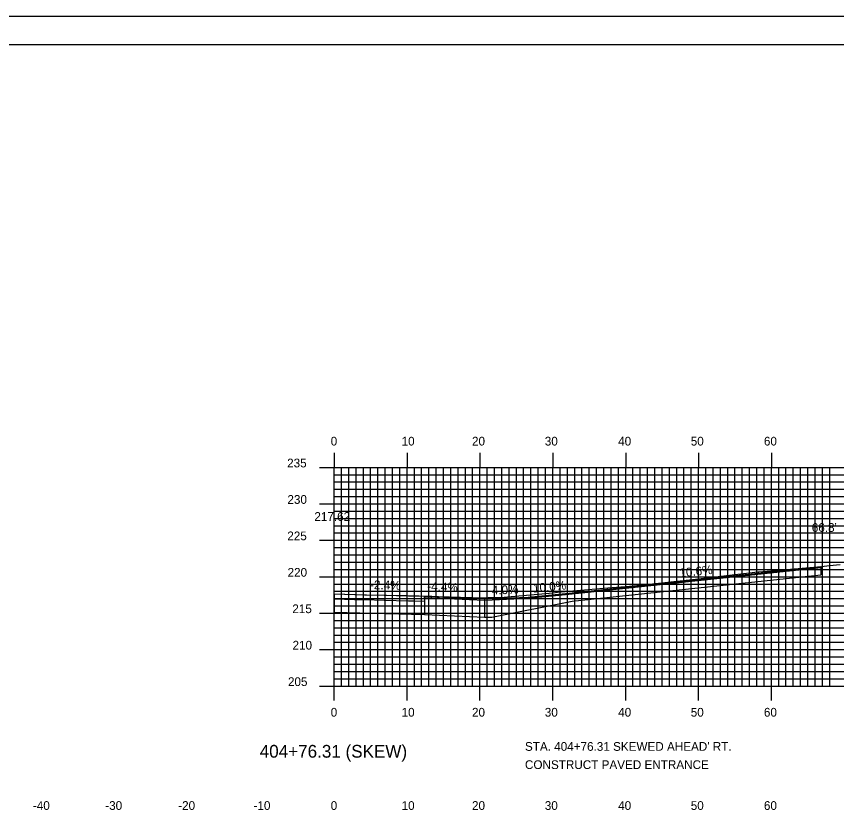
# Model space of a CAD drawing. Extents: x 851348 to 851692, y 364785 to 365005.
# Drawn here: x 851470.6 to 851583.1, y 364895.7 to 365005.1 of the extents above; entities that cross this region are included whole.
import ezdxf

# ---------------------------------------------------------------- set-up
doc = ezdxf.new("R2010")
doc.units = 0
for name, color, linetype in [('ANNOTATION', 7, 'Continuous'), ('BORDER', 7, 'Continuous'), ('D_Roadway_Centerline', 7, 'Continuous'), ('D_Roadway_Centerline_Text', 7, 'Continuous'), ('D_Roadway_Edge_Shoulder', 7, 'Continuous'), ('D_Text_Standard', 7, 'Continuous'), ('H_V ANNOTATION', 7, 'Continuous'), ('MAJOR', 7, 'Continuous'), ('MINOR', 7, 'Continuous'), ('PLOT BOUNDARY', 7, 'Continuous'), ('S_Roadway_Centerline', 7, 'Continuous')]:
    doc.layers.add(name, color=color, linetype=linetype)

msp = doc.modelspace()

# ---------------------------------------------------------------- linework, layer by layer
at = {"layer": 'ANNOTATION'}
for p, q in [((851580.99, 364929.65), (851580.99, 364928.48)), ((851526.57, 364925.56), (851526.57, 364924.2)), ((851535.83, 364922.7), (851546.83, 364924.86))]:
    msp.add_line(p, q, dxfattribs=at)
for points in [[(851534.83, 364925.2), (851540.83, 364925.44), (851546.83, 364926.04), (851580.99, 364929.65)], [(851534.84, 364925.03), (851540.84, 364925.27), (851546.85, 364925.87), (851580.99, 364929.48)], [(851546.83, 364924.86), (851580.99, 364928.47)], [(851514.18, 364925.19), (851516.98, 364925.12), (851518.35, 364925.09), (851521.04, 364925.02), (851524.38, 364924.94), (851525.09, 364924.93), (851526.57, 364924.89)], [(851514.19, 364925.86), (851514.19, 364923.36), (851526.57, 364923.06)], [(851526.57, 364925.56), (851526.57, 364923.06), (851534.83, 364922.7)], [(851534.83, 364925.2), (851534.83, 364922.7), (851535.83, 364922.7)]]:
    msp.add_lwpolyline(points, dxfattribs=at)
at = {"layer": 'BORDER'}
msp.add_lwpolyline([(851364.59, 364791.23), (851684.59, 364791.23), (851684.59, 365001.23), (851364.59, 365001.23)], close=True, dxfattribs=at)
at = {"layer": 'D_Roadway_Centerline'}
msp.add_lwpolyline([(851514.19, 364925.86), (851517, 364925.79), (851518.36, 364925.76), (851521.05, 364925.69), (851524.4, 364925.61), (851525.11, 364925.59), (851526.57, 364925.56), (851529.17, 364925.44), (851531.67, 364925.33), (851533.22, 364925.27), (851534.83, 364925.2)], dxfattribs=at)
at = {"layer": 'D_Roadway_Edge_Shoulder'}
msp.add_lwpolyline([(851526.57, 364925.56), (851534.83, 364925.2), (851534.83, 364924.95), (851526.57, 364925.31)], close=True, dxfattribs=at)
at = {"layer": 'MAJOR'}
for p, q in [((851514.19, 364945.24), (851514.19, 364943.23)), ((851524.19, 364945.24), (851524.19, 364943.23)), ((851534.19, 364945.24), (851534.19, 364943.23)), ((851544.19, 364945.24), (851544.19, 364943.23)), ((851554.19, 364945.24), (851554.19, 364943.23)), ((851564.19, 364945.24), (851564.19, 364943.23)), ((851574.19, 364945.24), (851574.19, 364943.23)), ((851512.19, 364943.23), (851514.19, 364943.23)), ((851514.19, 364943.23), (851654.19, 364943.23)), ((851514.19, 364913.23), (851514.19, 364943.23)), ((851514.19, 364913.23), (851514.19, 364943.23)), ((851514.19, 364943.23), (851654.19, 364943.23)), ((851524.19, 364913.23), (851524.19, 364943.23)), ((851534.19, 364913.23), (851534.19, 364943.23)), ((851544.19, 364913.23), (851544.19, 364943.23)), ((851554.19, 364913.23), (851554.19, 364943.23)), ((851564.19, 364913.23), (851564.19, 364943.23)), ((851574.19, 364913.23), (851574.19, 364943.23)), ((851512.19, 364938.23), (851514.19, 364938.23)), ((851514.19, 364938.23), (851654.19, 364938.23)), ((851512.19, 364933.23), (851514.19, 364933.23)), ((851514.19, 364933.23), (851654.19, 364933.23)), ((851512.19, 364928.23), (851514.19, 364928.23)), ((851514.19, 364928.23), (851654.19, 364928.23)), ((851512.19, 364923.23), (851514.19, 364923.23)), ((851514.19, 364923.23), (851654.19, 364923.23)), ((851512.19, 364918.23), (851514.19, 364918.23)), ((851514.19, 364918.23), (851654.19, 364918.23)), ((851512.19, 364913.23), (851514.19, 364913.23)), ((851514.19, 364913.23), (851654.19, 364913.23)), ((851514.19, 364913.23), (851654.19, 364913.23)), ((851514.19, 364911.23), (851514.19, 364913.23)), ((851524.19, 364911.23), (851524.19, 364913.23)), ((851534.19, 364911.23), (851534.19, 364913.23)), ((851544.19, 364911.23), (851544.19, 364913.23)), ((851554.19, 364911.23), (851554.19, 364913.23)), ((851564.19, 364911.23), (851564.19, 364913.23)), ((851574.19, 364911.23), (851574.19, 364913.23))]:
    msp.add_line(p, q, dxfattribs=at)
at = {"layer": 'MINOR'}
for p, q in [((851515.19, 364913.23), (851515.19, 364943.23)), ((851516.19, 364913.23), (851516.19, 364943.23)), ((851517.19, 364913.23), (851517.19, 364943.23)), ((851518.19, 364913.23), (851518.19, 364943.23)), ((851519.19, 364913.23), (851519.19, 364943.23)), ((851520.19, 364913.23), (851520.19, 364943.23)), ((851521.19, 364913.23), (851521.19, 364943.23)), ((851522.19, 364913.23), (851522.19, 364943.23)), ((851523.19, 364913.23), (851523.19, 364943.23)), ((851525.19, 364913.23), (851525.19, 364943.23)), ((851526.19, 364913.23), (851526.19, 364943.23)), ((851527.19, 364913.23), (851527.19, 364943.23)), ((851528.19, 364913.23), (851528.19, 364943.23)), ((851529.19, 364913.23), (851529.19, 364943.23)), ((851530.19, 364913.23), (851530.19, 364943.23)), ((851531.19, 364913.23), (851531.19, 364943.23)), ((851532.19, 364913.23), (851532.19, 364943.23)), ((851533.19, 364913.23), (851533.19, 364943.23)), ((851535.19, 364913.23), (851535.19, 364943.23)), ((851536.19, 364913.23), (851536.19, 364943.23)), ((851537.19, 364913.23), (851537.19, 364943.23)), ((851538.19, 364913.23), (851538.19, 364943.23)), ((851539.19, 364913.23), (851539.19, 364943.23)), ((851540.19, 364913.23), (851540.19, 364943.23)), ((851541.19, 364913.23), (851541.19, 364943.23)), ((851542.19, 364913.23), (851542.19, 364943.23)), ((851543.19, 364913.23), (851543.19, 364943.23)), ((851545.19, 364913.23), (851545.19, 364943.23)), ((851546.19, 364913.23), (851546.19, 364943.23)), ((851547.19, 364913.23), (851547.19, 364943.23)), ((851548.19, 364913.23), (851548.19, 364943.23)), ((851549.19, 364913.23), (851549.19, 364943.23)), ((851550.19, 364913.23), (851550.19, 364943.23)), ((851551.19, 364913.23), (851551.19, 364943.23)), ((851552.19, 364913.23), (851552.19, 364943.23)), ((851553.19, 364913.23), (851553.19, 364943.23)), ((851555.19, 364913.23), (851555.19, 364943.23)), ((851556.19, 364913.23), (851556.19, 364943.23)), ((851557.19, 364913.23), (851557.19, 364943.23)), ((851558.19, 364913.23), (851558.19, 364943.23)), ((851559.19, 364913.23), (851559.19, 364943.23)), ((851560.19, 364913.23), (851560.19, 364943.23)), ((851561.19, 364913.23), (851561.19, 364943.23)), ((851562.19, 364913.23), (851562.19, 364943.23)), ((851563.19, 364913.23), (851563.19, 364943.23)), ((851565.19, 364913.23), (851565.19, 364943.23)), ((851566.19, 364913.23), (851566.19, 364943.23)), ((851567.19, 364913.23), (851567.19, 364943.23)), ((851568.19, 364913.23), (851568.19, 364943.23)), ((851569.19, 364913.23), (851569.19, 364943.23)), ((851570.19, 364913.23), (851570.19, 364943.23)), ((851571.19, 364913.23), (851571.19, 364943.23)), ((851572.19, 364913.23), (851572.19, 364943.23)), ((851573.19, 364913.23), (851573.19, 364943.23)), ((851575.19, 364913.23), (851575.19, 364943.23)), ((851576.19, 364913.23), (851576.19, 364943.23)), ((851577.19, 364913.23), (851577.19, 364943.23)), ((851578.19, 364913.23), (851578.19, 364943.23)), ((851579.19, 364913.23), (851579.19, 364943.23)), ((851580.19, 364913.23), (851580.19, 364943.23)), ((851581.19, 364913.23), (851581.19, 364943.23)), ((851582.19, 364913.23), (851582.19, 364943.23)), ((851514.19, 364942.23), (851654.19, 364942.23)), ((851514.19, 364942.23), (851516.2, 364942.23)), ((851514.19, 364941.23), (851654.19, 364941.23)), ((851514.19, 364941.23), (851516.2, 364941.23)), ((851514.19, 364940.23), (851654.19, 364940.23)), ((851514.19, 364940.23), (851516.2, 364940.23)), ((851514.19, 364939.23), (851654.19, 364939.23)), ((851514.19, 364939.23), (851516.2, 364939.23)), ((851514.19, 364937.23), (851654.19, 364937.23)), ((851514.19, 364937.23), (851516.2, 364937.23)), ((851514.19, 364936.23), (851654.19, 364936.23)), ((851514.19, 364936.23), (851516.2, 364936.23)), ((851514.19, 364935.23), (851654.19, 364935.23)), ((851514.19, 364935.23), (851516.2, 364935.23)), ((851514.19, 364934.23), (851654.19, 364934.23)), ((851514.19, 364934.23), (851516.2, 364934.23)), ((851514.19, 364932.23), (851654.19, 364932.23)), ((851514.19, 364932.23), (851516.2, 364932.23)), ((851514.19, 364931.23), (851654.19, 364931.23)), ((851514.19, 364931.23), (851516.2, 364931.23)), ((851514.19, 364930.23), (851654.19, 364930.23)), ((851514.19, 364930.23), (851516.2, 364930.23)), ((851514.19, 364929.23), (851654.19, 364929.23)), ((851514.19, 364929.23), (851516.2, 364929.23)), ((851514.19, 364927.23), (851654.19, 364927.23)), ((851514.19, 364927.23), (851516.2, 364927.23)), ((851514.19, 364926.23), (851654.19, 364926.23)), ((851514.19, 364926.23), (851516.2, 364926.23)), ((851514.19, 364925.23), (851654.19, 364925.23)), ((851514.19, 364925.23), (851516.2, 364925.23)), ((851514.19, 364924.23), (851654.19, 364924.23)), ((851514.19, 364924.23), (851516.2, 364924.23)), ((851514.19, 364922.23), (851654.19, 364922.23)), ((851514.19, 364922.23), (851516.2, 364922.23)), ((851514.19, 364921.23), (851654.19, 364921.23)), ((851514.19, 364921.23), (851516.2, 364921.23)), ((851514.19, 364920.23), (851654.19, 364920.23)), ((851514.19, 364920.23), (851516.2, 364920.23)), ((851514.19, 364919.23), (851654.19, 364919.23)), ((851514.19, 364919.23), (851516.2, 364919.23)), ((851514.19, 364917.23), (851654.19, 364917.23)), ((851514.19, 364917.23), (851516.2, 364917.23)), ((851514.19, 364916.23), (851654.19, 364916.23)), ((851514.19, 364916.23), (851516.2, 364916.23)), ((851514.19, 364915.23), (851654.19, 364915.23)), ((851514.19, 364915.23), (851516.2, 364915.23)), ((851514.19, 364914.23), (851654.19, 364914.23)), ((851514.19, 364914.23), (851516.2, 364914.23))]:
    msp.add_line(p, q, dxfattribs=at)
at = {"layer": 'PLOT BOUNDARY'}
msp.add_lwpolyline([(851348.4, 364785.11), (851688.4, 364785.11), (851688.4, 365005.11), (851348.4, 365005.11)], close=True, dxfattribs=at)
at = {"layer": 'S_Roadway_Centerline'}
msp.add_lwpolyline([(851514.19, 364925.86), (851518.61, 364925.76), (851524.12, 364925.63), (851527.57, 364925.57), (851528.52, 364925.53), (851533.03, 364925.4), (851535.07, 364925.35), (851535.33, 364925.37), (851537.03, 364925.4), (851537.99, 364925.48), (851543.2, 364925.94), (851543.7, 364925.99), (851544.24, 364926.02), (851544.84, 364926.1), (851551.15, 364926.66), (851555.33, 364927), (851556.99, 364927.18), (851563.37, 364927.84), (851572.32, 364928.88), (851572.46, 364928.88), (851574.16, 364929.05), (851577.86, 364929.38), (851581.07, 364929.65), (851582.15, 364929.76), (851583.61, 364929.92)], dxfattribs=at)

# ---------------------------------------------------------------- texts
at = {"layer": 'ANNOTATION'}
for s, rotation, p in [('10.6%', 6.0322, (851561.63, 364928.14)), ('-2.4%', 358.6072, (851519.1, 364926.54)), ('-4.4%', 357.498, (851526.94, 364926.34)), ('10.0%', 5.7106, (851541.53, 364926.04)), ('4.0%', 2.2906, (851535.84, 364925.77))]:
    msp.add_text(s, height=1.2, rotation=rotation, dxfattribs=at).set_placement(p)
at = {"layer": 'D_Roadway_Centerline_Text'}
msp.add_text('217.62', height=1.2, dxfattribs=at).set_placement((851511.47, 364935.89))
at = {"layer": 'D_Text_Standard'}
for s, p in [("66.8'", (851579.73, 364934.38)), ("STA. 404+76.31 SKEWED AHEAD' RT.", (851540.37, 364904.34)), ('CONSTRUCT PAVED ENTRANCE', (851540.37, 364901.84))]:
    msp.add_text(s, height=1.2, dxfattribs=at).set_placement(p)
at = {"layer": 'H_V ANNOTATION'}
for s, height, p in [('0', 1.2, (851513.71, 364946.23)), ('10', 1.2, (851523.44, 364946.23)), ('20', 1.2, (851533.1, 364946.23)), ('30', 1.2, (851543.09, 364946.23)), ('40', 1.2, (851553.16, 364946.23)), ('50', 1.2, (851563.12, 364946.23)), ('60', 1.2, (851573.16, 364946.23)), ('235', 1.2, (851507.73, 364943.23)), ('230', 1.2, (851507.77, 364938.23)), ('225', 1.2, (851507.75, 364933.23)), ('220', 1.2, (851507.79, 364928.23)), ('215', 1.2, (851508.44, 364923.23)), ('210', 1.2, (851508.47, 364918.23)), ('205', 1.2, (851507.84, 364913.23)), ('0', 1.2, (851513.71, 364909.03)), ('10', 1.2, (851523.44, 364909.03)), ('20', 1.2, (851533.1, 364909.03)), ('30', 1.2, (851543.09, 364909.03)), ('40', 1.2, (851553.16, 364909.03)), ('50', 1.2, (851563.12, 364909.03)), ('60', 1.2, (851573.16, 364909.03)), ('404+76.31 (SKEW)', 1.75, (851503.97, 364903.4)), ('-40', 1.2, (851472.84, 364896.23)), ('-30', 1.2, (851482.77, 364896.23)), ('-20', 1.2, (851492.78, 364896.23)), ('-10', 1.2, (851503.12, 364896.23)), ('0', 1.2, (851513.71, 364896.23)), ('10', 1.2, (851523.44, 364896.23)), ('20', 1.2, (851533.1, 364896.23)), ('30', 1.2, (851543.09, 364896.23)), ('40', 1.2, (851553.16, 364896.23)), ('50', 1.2, (851563.12, 364896.23)), ('60', 1.2, (851573.16, 364896.23))]:
    msp.add_text(s, height=height, dxfattribs=at).set_placement(p)
at = {"layer": 'MAJOR'}
msp.add_text('-', height=0.012, dxfattribs=at).set_placement((851514.18, 364913.23))

doc.saveas('drawing.dxf')
